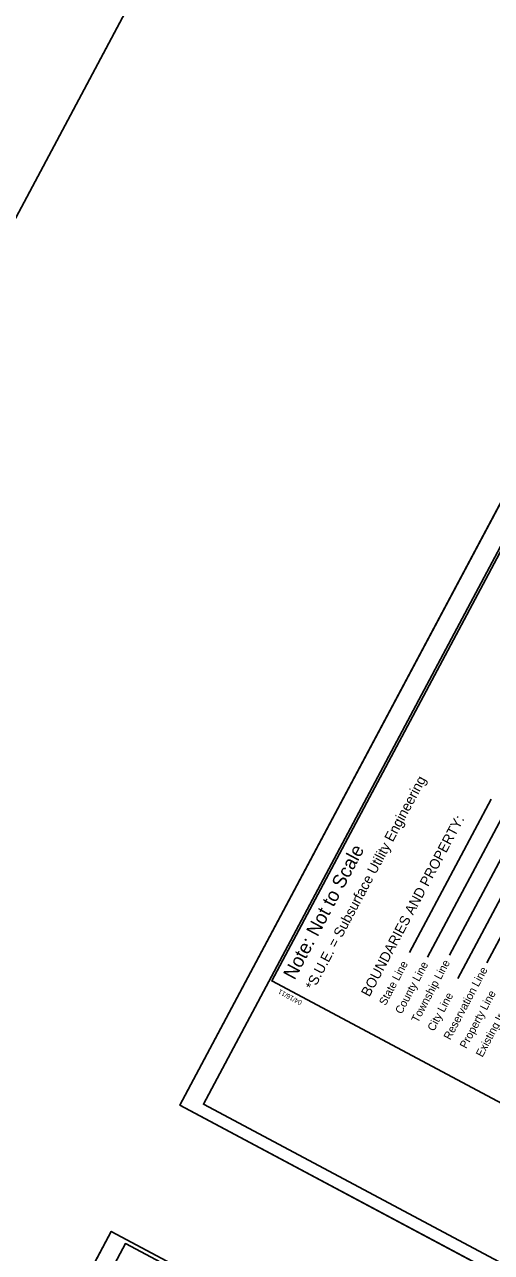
# Model space of a CAD drawing. Extents: x 1970823 to 1988115, y 770601 to 786368.
# Drawn here: x 1979340 to 1979851, y 778250 to 779592 of the extents above; entities that cross this region are included whole.
import ezdxf

# ---------------------------------------------------------------- set-up
doc = ezdxf.new("R2010")
doc.units = 0
for name, color, linetype in [('Old_Level_51', 7, 'Continuous'), ('Sheet Cutting Line CELL', 7, 'Continuous'), ('Sheet Plot Border Inside CELL', 7, 'Continuous'), ('Sheet Plot Border Outside CELL', 7, 'Continuous'), ('Sheet Summary Guardrail CELL', 7, 'Continuous'), ('Sheet Symbology CELL', 7, 'Continuous')]:
    doc.layers.add(name, color=color, linetype=linetype)

msp = doc.modelspace()

# ---------------------------------------------------------------- linework, layer by layer
at = {"layer": 'Old_Level_51'}
msp.add_lwpolyline([(1975574.8, 786367.7), (1970823, 777450.8), (1976647.6, 774346.9), (1981399.3, 783263.8)], close=True, dxfattribs=at)
at = {"layer": 'Sheet Cutting Line CELL'}
for p, q in [((1976647.6, 774346.9), (1981399.3, 783263.8)), ((1980301.6, 779897.3), (1979509.7, 778411.1)), ((1979509.7, 778411.1), (1980480.4, 777893.8)), ((1979434.7, 778273), (1978643, 776787.2))]:
    msp.add_line(p, q, dxfattribs=at)
at = {"layer": 'Sheet Plot Border Inside CELL'}
for points in [[(1980466.7, 777915.8), (1981250.5, 779386.5), (1980319.3, 779882.7), (1979535.6, 778412)], [(1979597.8, 776293.2), (1980381.3, 777763.4), (1979450.2, 778259.6), (1978666.7, 776789.3)]]:
    msp.add_lwpolyline(points, close=True, dxfattribs=at)
at = {"layer": 'Sheet Plot Border Outside CELL'}
for points in [[(1975574.8, 786367.7), (1970823, 777450.8), (1976647.6, 774346.9), (1981399.3, 783263.8)], [(1980480.4, 777893.8), (1981272.4, 779379.9), (1980301.6, 779897.3), (1979509.7, 778411.1)], [(1979609.3, 776272.3), (1980401.1, 777758), (1979434.7, 778273), (1978643, 776787.2)]]:
    msp.add_lwpolyline(points, close=True, dxfattribs=at)
at = {"layer": 'Sheet Symbology CELL'}
for p, q in [((1979850.2, 778745.4), (1979760.8, 778577.7)), ((1979867.8, 778736), (1979780.8, 778572.7)), ((1979885.5, 778726.5), (1979804.7, 778575)), ((1979903.1, 778717.1), (1979813.8, 778549.5)), ((1979920.8, 778707.7), (1979845.5, 778566.5))]:
    msp.add_line(p, q, dxfattribs=at)
msp.add_lwpolyline([(1980315.7, 779870.5), (1979610.3, 778546.7), (1980536, 778053.4), (1981241.4, 779377.2)], close=True, dxfattribs=at)

# ---------------------------------------------------------------- texts
at = {"layer": 'Sheet Summary Guardrail CELL'}
msp.add_text('04/16/11', height=5.25, rotation=151.9471, dxfattribs=at).set_placement((1979644, 778524.6))
at = {"layer": 'Sheet Symbology CELL'}
for s, height, p in [('*S.U.E. = Subsurface Utility Engineering', 11, (1979656.3, 778535.9)), ('BOUNDARIES AND PROPERTY:', 11, (1979717.1, 778528.6)), ('Note: Not to Scale', 15, (1979635.3, 778547)), ('State Line', 8.75, (1979734.8, 778519.2)), ('County Line', 8.75, (1979752.4, 778509.8)), ('Township Line', 8.75, (1979770.1, 778500.4)), ('Reservation Line', 8.75, (1979805.4, 778481.6)), ('Existing Iron Pin', 8.75, (1979840.7, 778462.7)), ('City Line', 8.75, (1979787.7, 778491)), ('Property Line', 8.75, (1979823, 778472.1))]:
    msp.add_text(s, height=height, rotation=61.9471, dxfattribs=at).set_placement(p)

doc.saveas('drawing.dxf')
